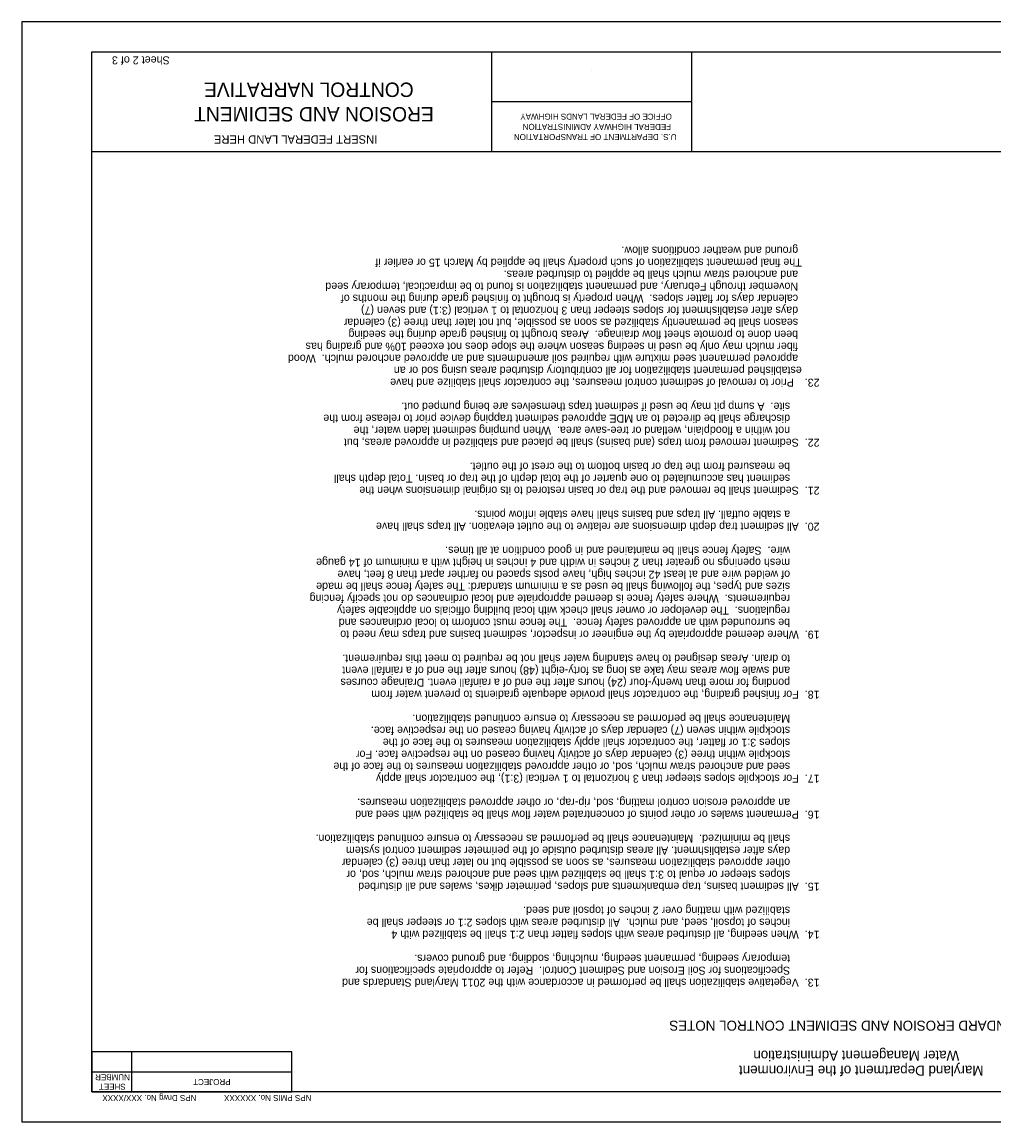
# Model space of a CAD drawing. Extents: x 419665 to 429598, y 426565 to 429085.
# Drawn here: x 425551 to 426523, y 426759 to 427859 of the extents above; entities that cross this region are included whole.
import ezdxf

# ---------------------------------------------------------------- set-up
doc = ezdxf.new("R2010")
doc.units = 0
for name, color, linetype in [('AUX_01', 7, 'Continuous'), ('D_Dimensions', 7, 'Continuous'), ('D_EFL_Handles', 7, 'Continuous'), ('D_Plot_Shape', 7, 'Continuous'), ('D_Sheet', 7, 'Continuous'), ('D_Sheet_Number', 7, 'Continuous')]:
    doc.layers.add(name, color=color, linetype=linetype)

msp = doc.modelspace()

# ---------------------------------------------------------------- linework, layer by layer
at = {"layer": 'D_Plot_Shape'}
msp.add_lwpolyline([(425550.6, 426759.4), (427250.6, 426759.4), (427250.6, 427859.4), (425550.6, 427859.4)], close=True, dxfattribs=at)
at = {"layer": 'D_Sheet'}
for p, q in [((426020.6, 427729.4), (426020.6, 427829.4)), ((426220.6, 427729.4), (426220.6, 427829.4)), ((426120.6, 427810.6), (426120.6, 427810.6)), ((426220.6, 427779.7), (426020.6, 427779.7)), ((427180.6, 427729.4), (425620.6, 427729.4)), ((425660.6, 426789.4), (425660.6, 426829.4)), ((425620.6, 426809.4), (425820.6, 426809.4))]:
    msp.add_line(p, q, dxfattribs=at)
msp.add_lwpolyline([(427180.6, 427829.4), (427180.6, 427729.4), (427180.6, 426789.4), (425620.6, 426789.4), (425620.6, 427729.4), (425620.6, 427829.4), (427180.6, 427829.4)], dxfattribs=at)
msp.add_lwpolyline([(425620.6, 426789.4), (425820.6, 426789.4), (425820.6, 426829.4), (425620.6, 426829.4)], close=True, dxfattribs=at)

# ---------------------------------------------------------------- texts
at = {"layer": 'AUX_01'}
for s, p in [('ground and weather conditions allow.', (426326.7, 427634.7)), ('      The final permanent stabilization of such property shall be applied by March 15 or earlier if ', (426348.2, 427622.7)), ('and anchored straw mulch shall be applied to disturbed areas.', (426326.7, 427610.7)), ('November through February, and permanent stabilization is found to be impractical, temporary seed ', (426326.7, 427598.7)), ('calendar days for flatter slopes.  When property is brought to finished grade during the months of ', (426326.7, 427586.7)), ('days after establishment for slopes steeper than 3 horizontal to 1 vertical (3:1) and seven (7) ', (426326.7, 427574.7)), ('season shall be permanently stabilized as soon as possible, but not later than three (3) calendar ', (426326.7, 427562.7)), ('been done to promote sheet flow drainage.  Areas brought to finished grade during the seeding ', (426326.7, 427550.7)), ('fiber mulch may only be used in seeding season where the slope does not exceed 10% and grading has ', (426326.7, 427538.7)), ('approved permanent seed mixture with required soil amendments and an approved anchored mulch.  Wood ', (426326.7, 427526.7)), ('      established permanent stabilization for all contributory disturbed areas using sod or an ', (426348.2, 427514.7)), ('Prior to removal of sediment control measures, the contractor shall stabilize and have', (426322.5, 427502.7)), ('23.  ', (426348.2, 427502.7)), ('site.  A sump pit may be used if sediment traps themselves are being pumped out.', (426318.7, 427478.7)), ('discharge shall be directed to an MDE approved sediment trapping device prior to release from the ', (426318.7, 427466.7)), ('not within a floodplain, wetland or tree-save area.  When pumping sediment laden water, the ', (426318.7, 427454.7)), ('22.  Sediment removed from traps (and basins) shall be placed and stabilized in approved areas, but ', (426348.2, 427442.7)), ('be measured from the trap or basin bottom to the crest of the outlet.', (426318.7, 427418.7)), ('sediment has accumulated to one quarter of the total depth of the trap or basin. Total depth shall ', (426318.7, 427406.7)), ('21.  Sediment shall be removed and the trap or basin restored to its original dimensions when the ', (426348.2, 427394.7)), ('a stable outfall. All traps and basins shall have stable inflow points.', (426318.7, 427370.7)), ('20.  All sediment trap depth dimensions are relative to the outlet elevation. All traps shall have ', (426348.2, 427358.7)), ('wire.  Safety fence shall be maintained and in good condition at all times.', (426318.7, 427334.7)), ('mesh openings no greater than 2 inches in width and 4 inches in height with a minimum of 14 gauge ', (426318.7, 427322.7)), ('of welded wire and at least 42 inches high, have posts spaced no farther apart than 8 feet, have ', (426318.7, 427310.7)), ('sizes and types, the following shall be used as a minimum standard: The safety fence shall be made ', (426318.7, 427298.7)), ('requirements.  Where safety fence is deemed appropriate and local ordinances do not specify fencing ', (426318.7, 427286.7)), ('regulations.  The developer or owner shall check with local building officials on applicable safety ', (426318.7, 427274.7)), ('be surrounded with an approved safety fence.  The fence must conform to local ordinances and ', (426318.7, 427262.7)), ('19.  Where deemed appropriate by the engineer or inspector, sediment basins and traps may need to ', (426348.2, 427250.7)), ('to drain. Areas designed to have standing water shall not be required to meet this requirement.', (426318.7, 427226.7)), ('and swale flow areas may take as long as forty-eight (48) hours after the end of a rainfall event ', (426318.7, 427214.7)), ('ponding for more than twenty-four (24) hours after the end of a rainfall event. Drainage courses ', (426318.7, 427202.7)), ('18.  For finished grading, the contractor shall provide adequate gradients to prevent water from ', (426348.2, 427190.7)), ('Maintenance shall be performed as necessary to ensure continued stabilization.', (426318.7, 427166.7)), ('stockpile within seven (7) calendar days of activity having ceased on the respective face. ', (426318.7, 427154.7)), ('slopes 3:1 or flatter, the contractor shall apply stabilization measures to the face of the ', (426318.7, 427142.7)), ('stockpile within three (3) calendar days of activity having ceased on the respective face. For ', (426318.7, 427130.7)), ('seed and anchored straw mulch, sod, or other approved stabilization measures to the face of the ', (426318.7, 427118.7)), ('17.  For stockpile slopes steeper than 3 horizontal to 1 vertical (3:1), the contractor shall apply ', (426348.2, 427106.7)), ('an approved erosion control matting, sod, rip-rap, or other approved stabilization measures.', (426318.7, 427082.7)), ('16.  Permanent swales or other points of concentrated water flow shall be stabilized with seed and ', (426348.2, 427070.7)), ('shall be minimized.  Maintenance shall be performed as necessary to ensure continued stabilization.', (426318.7, 427046.7)), ('days after establishment. All areas disturbed outside of the perimeter sediment control system ', (426318.7, 427034.7)), ('other approved stabilization measures, as soon as possible but no later than three (3) calendar ', (426318.7, 427022.7)), ('slopes steeper or equal to 3:1 shall be stabilized with seed and anchored straw mulch, sod, or ', (426318.7, 427010.7)), ('15.  All sediment basins, trap embankments and slopes, perimeter dikes, swales and all disturbed ', (426348.2, 426998.7)), ('stabilized with matting over 2 inches of topsoil and seed.', (426318.7, 426974.7)), ('inches of topsoil, seed, and mulch.  All disturbed areas with slopes 2:1 or steeper shall be ', (426318.7, 426962.7)), ('14.  When seeding, all disturbed areas with slopes flatter than 2:1 shall be stabilized with 4 ', (426348.2, 426950.7)), ('temporary seeding, permanent seeding, mulching, sodding, and ground covers.', (426318.7, 426926.7)), ('Specifications for Soil Erosion and Sediment Control.  Refer to appropriate specifications for ', (426318.7, 426914.7)), ('13.  Vegetative stabilization shall be performed in accordance with the 2011 Maryland Standards and ', (426348.2, 426902.7))]:
    msp.add_text(s, height=8, rotation=180, dxfattribs=at).set_placement(p)
at = {"layer": 'D_Dimensions'}
for s, p in [('STANDARD EROSION AND SEDIMENT CONTROL NOTES', (426560.5, 426860.7)), ('Water Management Administration', (426487.8, 426830.7)), ('Maryland Department of the Environment', (426512.1, 426815.7))]:
    msp.add_text(s, height=10, rotation=180, dxfattribs=at).set_placement(p)
at = {"layer": 'D_EFL_Handles'}
msp.add_text('Sheet 2 of 3', height=8, rotation=180, dxfattribs=at).set_placement((425698.3, 427825))
at = {"layer": 'D_Sheet'}
for s, height, p in [('CONTROL NARRATIVE', 14.4, (425942.3, 427798.8)), ('EROSION AND SEDIMENT', 14.4, (425962.4, 427774.3)), ('OFFICE OF FEDERAL LANDS HIGHWAY', 6, (426200.5, 427767.7)), ('FEDERAL HIGHWAY ADMINISTRATION', 6, (426199.7, 427757.5)), ('INSERT FEDERAL LAND HERE', 8.4, (425906, 427746.1)), ('U.S. DEPARTMENT OF TRANSPORTATION', 6, (426205.2, 427747.3)), ('NUMBER', 6, (425658.5, 426807.2)), ('PROJECT', 6, (425759.2, 426802.4)), ('SHEET', 6, (425654.3, 426797.6))]:
    msp.add_text(s, height=height, rotation=180, dxfattribs=at).set_placement(p)
at = {"layer": 'D_Sheet_Number'}
for s, p in [('NPS Drwg No. XXX/XXXX', (425725.1, 426786.4)), ('NPS PMIS No. XXXXXX', (425840.1, 426786.4))]:
    msp.add_text(s, height=6, rotation=180, dxfattribs=at).set_placement(p)

doc.saveas('drawing.dxf')
